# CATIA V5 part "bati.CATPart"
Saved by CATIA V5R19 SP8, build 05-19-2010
Part number: squelette bati
Bounding box of the stored display mesh (mm): x 0 to 0, y 0 to 39, z -12 to 31
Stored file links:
  C:\Users\rcousturie\Desktop\EU_thinkMotion\iao\IAO_MMS_Groupe1\glenerrant\glenerrant\Nouveau dossier\bati.CATPart
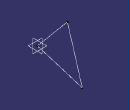
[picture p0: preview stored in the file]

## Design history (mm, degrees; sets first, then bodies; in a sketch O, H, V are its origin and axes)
Set1
  Line1: type PtPt, FirstPoint Point1, SecondPoint Point2
  Point1: stored without definition
  Point2: stored without definition
  Line2: type PtPt, FirstPoint Point3, SecondPoint Point4
  Point3: stored without definition
  Point4: stored without definition
  Line3: type PtPt, FirstPoint Point5, SecondPoint Point6
  Point5: stored without definition
  Point6: stored without definition
Body1 (main body)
